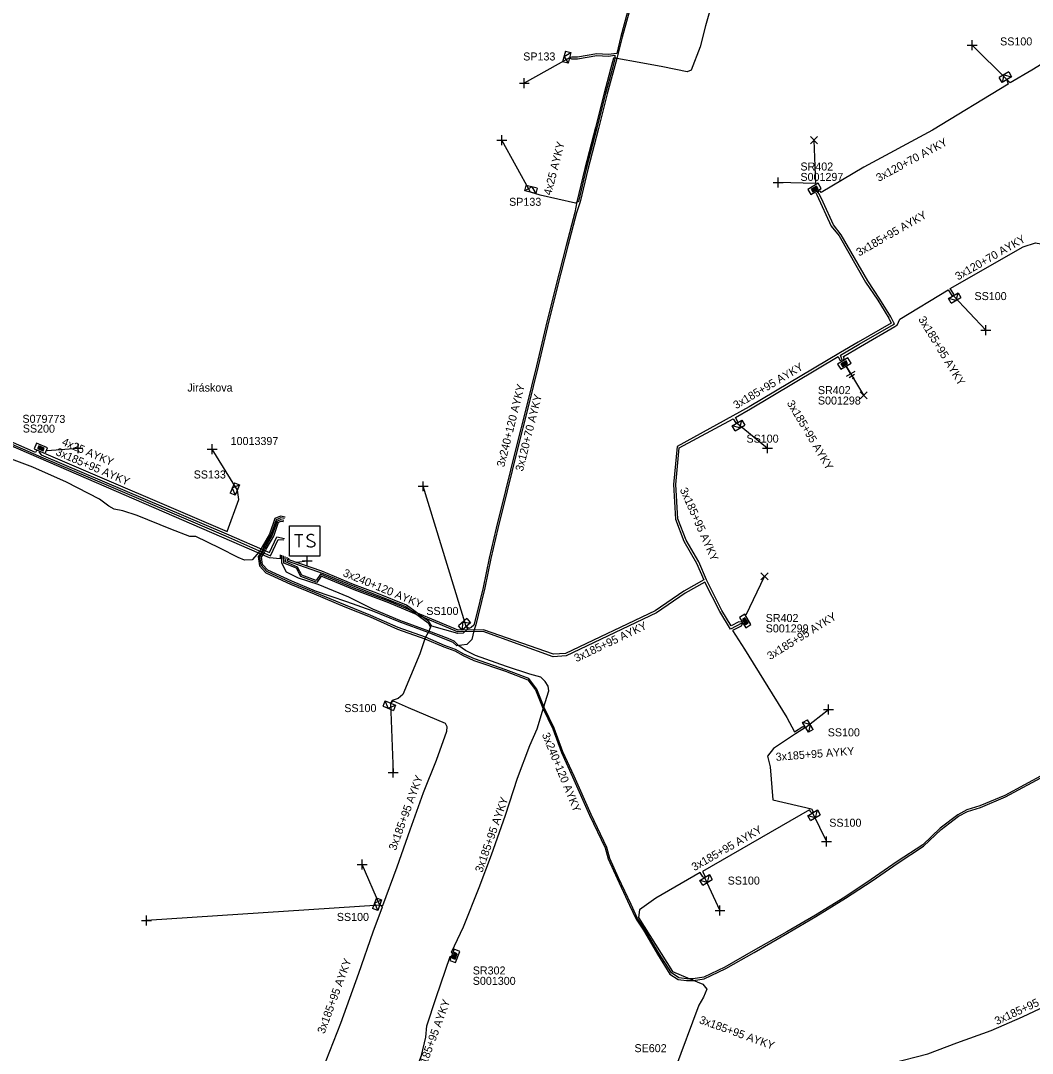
# Model space of a CAD drawing. Extents: x -763093 to -760976, y -1155572 to -1152009.
# Drawn here: x -762038.3 to -761911.9, y -1154879.5 to -1154750.4 of the extents above; entities that cross this region are included whole.
import ezdxf

# ---------------------------------------------------------------- set-up
doc = ezdxf.new("R2010")
doc.units = 0
for name, color, linetype in [('Vrstva 1', 7, 'Continuous'), ('Vrstva 14', 7, 'Continuous'), ('Vrstva 15', 7, 'Continuous'), ('Vrstva 25', 7, 'Continuous'), ('Vrstva 26', 7, 'Continuous'), ('Vrstva 27', 7, 'Continuous'), ('Vrstva 28', 7, 'Continuous'), ('Vrstva 29', 7, 'Continuous'), ('Vrstva 30', 7, 'Continuous'), ('Vrstva 31', 7, 'Continuous'), ('Vrstva 33', 7, 'Continuous'), ('Vrstva 34', 7, 'Continuous'), ('Vrstva 5', 7, 'Continuous'), ('Vrstva 59', 7, 'Continuous'), ('Vrstva 6', 7, 'Continuous'), ('Vrstva 8', 7, 'Continuous'), ('Vrstva 9', 7, 'Continuous')]:
    doc.layers.add(name, color=color, linetype=linetype)

# ---------------------------------------------------------------- blocks, each defined once
blk = doc.blocks.new('NN800')
at = {"layer": 'Vrstva 1'}
for points in [[(-0.44, 0.44), (0.44, -0.44)], [(-0.44, -0.44), (0.44, 0.44)]]:
    blk.add_lwpolyline(points, dxfattribs=at)
blk = doc.blocks.new('NN620')
at = {"layer": 'Vrstva 8'}
for points in [[(0.75, 0), (-0.75, 0)], [(-0.75, 0), (-0.75, -0.75)], [(0.75, -0.75), (0.75, 0)], [(-0.75, -0.75), (0.75, -0.75)], [(0.37, -0.18), (-0.38, -0.18)], [(-0.38, -0.18), (-0.38, -0.56)], [(-0.38, -0.56), (0.37, -0.56)], [(0.32, -0.23), (-0.33, -0.23)], [(-0.33, -0.23), (-0.33, -0.51)], [(-0.33, -0.51), (0.32, -0.51)], [(0.27, -0.27), (-0.28, -0.27)], [(-0.28, -0.27), (-0.28, -0.46)], [(-0.28, -0.46), (0.27, -0.46)], [(0.23, -0.32), (-0.23, -0.32)], [(-0.23, -0.32), (-0.23, -0.42)], [(-0.23, -0.42), (0.23, -0.42)], [(-0.19, -0.37), (0.19, -0.37)], [(0.23, -0.42), (0.23, -0.32)], [(0.27, -0.46), (0.27, -0.27)], [(0.32, -0.51), (0.32, -0.23)], [(0.37, -0.56), (0.37, -0.18)]]:
    blk.add_lwpolyline(points, dxfattribs=at)
blk = doc.blocks.new('NN630')
at = {"layer": 'Vrstva 9'}
for points in [[(0, -0.7), (-0.7, 0)], [(-0.7, -0.7), (-0.7, 0), (0.7, 0), (0.7, -0.7)], [(-0.7, -0.7), (0.7, -0.7)], [(0, -0.7), (0.7, 0)]]:
    blk.add_lwpolyline(points, dxfattribs=at)
blk = doc.blocks.new('NN810')
at = {"layer": 'Vrstva 14'}
for points in [[(0, -0.64), (0, -1.89)], [(0.63, -1.89), (-0.62, -1.89)], [(0.39, -2.2), (-0.4, -2.2)], [(0, -2.52), (-0.12, -2.52)], [(0.14, -2.52), (0, -2.52)]]:
    blk.add_lwpolyline(points, dxfattribs=at)
blk = doc.blocks.new('NN640')
at = {"layer": 'Vrstva 6'}
for points in [[(-1.89, 1.89), (1.89, 1.89)], [(-1.89, -1.89), (-1.89, 1.89)], [(1.89, 1.89), (1.89, -1.89)], [(-1.26, 0.79), (-0.22, 0.79)], [(-0.73, 0.79), (-0.73, -0.79)], [(1.2, 0.66), (0.94, 0.79), (0.66, 0.79), (0.41, 0.66), (0.28, 0.47), (0.28, 0.41), (0.41, 0.22), (1.13, -0.16), (1.26, -0.32), (1.26, -0.47), (1.13, -0.66), (0.91, -0.79), (0.63, -0.79), (0.5, -0.73), (0.28, -0.6)], [(1.89, -1.89), (-1.89, -1.89)]]:
    blk.add_lwpolyline(points, dxfattribs=at)

msp = doc.modelspace()

# ---------------------------------------------------------------- linework, layer by layer
at = {"layer": 'Vrstva 5'}
for points in [[(-761951, -1154744.92), (-761952.76, -1154751.08), (-761953.43, -1154753.72), (-761954.52, -1154756.65), (-761955.04, -1154756.86), (-761958.1, -1154756.22), (-761961.03, -1154755.67), (-761963.82, -1154755.16), (-761963.92, -1154755.14), (-761964.25, -1154755.13), (-761964.6, -1154756.5), (-761965.42, -1154759.49), (-761966.51, -1154763.8), (-761967.84, -1154768.93), (-761968.81, -1154773.09), (-761969.08, -1154774.42), (-761970.16, -1154778.52), (-761971.44, -1154783.56), (-761972.7, -1154788.62), (-761973.86, -1154793.57), (-761975.12, -1154798.66), (-761976.49, -1154804.09), (-761977.73, -1154809.16), (-761978.91, -1154813.86), (-761979.76, -1154817.62), (-761980.53, -1154821.27), (-761981.36, -1154824.7), (-761981.67, -1154825.98), (-761982.02, -1154826.25), (-761982.31, -1154826.4), (-761982.63, -1154826.13), (-761982.49, -1154826.49), (-761983.04, -1154826.98), (-761983.69, -1154827), (-761986.95, -1154826.09), (-761987.31, -1154825.5), (-761990.09, -1154823.48), (-761993.79, -1154821.99), (-761996.71, -1154820.88), (-762000.66, -1154819.24), (-762004.8, -1154817.8), (-762004.81, -1154817.6)], [(-761961.87, -1154747.79), (-761963.14, -1154752.5), (-761963.82, -1154755.16), (-761965.04, -1154759.59), (-761966.13, -1154763.9), (-761967.46, -1154769.03), (-761968.41, -1154773.1), (-761968.88, -1154774.47), (-761969.96, -1154778.58), (-761971.24, -1154783.6), (-761972.5, -1154788.66), (-761973.66, -1154793.61), (-761974.92, -1154798.7), (-761976.29, -1154804.13), (-761977.53, -1154809.2), (-761978.71, -1154813.9), (-761979.56, -1154817.66), (-761980.33, -1154821.31), (-761981.16, -1154824.74), (-761981.45, -1154825.94), (-761981.68, -1154826.7), (-761981.95, -1154827.77), (-761982.57, -1154828.4), (-761983.82, -1154828.58), (-761984.25, -1154828.13), (-761984.97, -1154827.84), (-761987.39, -1154826.9), (-761991.02, -1154825.57), (-761994.38, -1154824.17), (-761997.55, -1154823.07), (-762001.48, -1154821.71), (-762004.43, -1154820.49), (-762007.42, -1154819.12), (-762008.07, -1154818.4), (-762008.21, -1154817.47), (-762007.9, -1154817.05), (-762007.62, -1154816.48), (-762006.68, -1154814.87), (-762006.07, -1154813.11), (-762005.76, -1154812.97), (-762005.48, -1154813.03)], [(-761962.07, -1154747.75), (-761963.34, -1154752.44), (-761963.82, -1154754.53), (-761964.91, -1154754.68), (-761966.33, -1154754.6), (-761968.75, -1154755.01), (-761969.45, -1154755.01), (-761969.74, -1154755.1), (-761969.47, -1154755.21), (-761968.73, -1154755.21), (-761966.31, -1154754.8), (-761964.91, -1154754.88), (-761964.08, -1154754.77), (-761964.06, -1154755.18), (-761964.41, -1154756.55), (-761965.23, -1154759.54), (-761966.32, -1154763.85), (-761967.65, -1154768.98), (-761968.6, -1154773.05), (-761968.98, -1154773.27), (-761973.39, -1154772.25), (-761974.62, -1154771.89)], [(-761908.65, -1154754.61), (-761911.99, -1154756.63), (-761914.71, -1154758.2), (-761915.11, -1154757.81)], [(-762181.23, -1154758.53), (-762171.67, -1154757.36), (-762165.37, -1154757.31), (-762159.93, -1154757.58), (-762150.92, -1154758.82), (-762136.22, -1154763.17), (-762128.28, -1154765.54), (-762121.5, -1154768.45), (-762108.38, -1154774.11), (-762101.51, -1154777.12), (-762093.99, -1154780.16), (-762079.09, -1154786.61), (-762062.62, -1154793.49), (-762050.39, -1154798.57), (-762036.07, -1154804.84), (-762027.38, -1154808.52), (-762012.7, -1154814.81), (-762007.08, -1154817.32), (-762006.12, -1154815.27), (-762005.4, -1154815.32)], [(-761915.11, -1154757.81), (-761914.95, -1154758.38), (-761924.41, -1154764.13), (-761932.97, -1154768.74), (-761938.31, -1154771.92), (-761938.43, -1154771.76), (-761938.75, -1154771.83)], [(-761938.98, -1154771.97), (-761938.94, -1154772.04), (-761938.84, -1154772.2), (-761937.04, -1154776.12), (-761936.04, -1154777.35), (-761932.75, -1154783.1), (-761931.23, -1154785.39), (-761929.87, -1154787.62), (-761929.54, -1154788.23), (-761933.69, -1154790.62), (-761935.89, -1154791.9), (-761947.3, -1154798.68), (-761956.3, -1154803.65), (-761956.75, -1154808.4), (-761956.49, -1154812.74), (-761955.44, -1154815.49), (-761953.86, -1154818.22), (-761952.94, -1154820.31), (-761955.44, -1154821.73), (-761959.04, -1154824.17), (-761970.23, -1154829.5), (-761971.73, -1154829.62), (-761980.47, -1154826.57), (-761983.63, -1154826.61), (-761992.22, -1154823.02), (-761996.56, -1154821.38), (-762000.82, -1154819.61), (-762001.38, -1154820.4), (-762003.17, -1154819.72), (-762003.7, -1154818.71), (-762005.23, -1154818.07), (-762005.25, -1154817.41)], [(-761935.67, -1154792.86), (-761935.9, -1154792.26), (-761933.55, -1154790.88), (-761929.27, -1154788.41), (-761929.14, -1154788.33), (-761929.21, -1154788.21), (-761929.61, -1154787.47), (-761930.97, -1154785.23), (-761932.49, -1154782.94), (-761935.8, -1154777.19), (-761936.78, -1154775.96), (-761938.07, -1154773.14), (-761938.57, -1154772.07), (-761938.7, -1154771.89), (-761938.86, -1154771.9)], [(-761921.81, -1154784.8), (-761921.75, -1154784.6), (-761922.17, -1154783.92), (-761913.09, -1154778.7), (-761911.53, -1154778.2), (-761909.53, -1154778.59), (-761907.79, -1154780.05), (-761903.33, -1154784.19), (-761898.58, -1154793.13), (-761899.39, -1154793.63), (-761899.45, -1154793.83)], [(-761935.55, -1154792.79), (-761935.41, -1154792.66), (-761935.53, -1154792.4), (-761933.39, -1154791.14), (-761929.11, -1154788.67), (-761928.97, -1154788.57), (-761928.8, -1154788.48), (-761928.48, -1154787.75), (-761922.42, -1154784.07), (-761922, -1154784.77), (-761921.81, -1154784.8)], [(-761948.29, -1154825.6), (-761948.57, -1154825.55), (-761949.54, -1154826.07), (-761950.7, -1154824.14), (-761952.61, -1154820.31), (-761953.6, -1154818.08), (-761955.16, -1154815.35), (-761956.19, -1154812.68), (-761956.45, -1154808.4), (-761956.02, -1154803.83), (-761949.29, -1154800.2), (-761949.02, -1154800.67), (-761948.8, -1154800.73), (-761948.76, -1154800.5), (-761949.01, -1154800.04), (-761947.14, -1154798.94), (-761936.16, -1154792.41), (-761935.97, -1154792.88), (-761935.78, -1154792.92)], [(-762036.31, -1154804.17), (-762036.42, -1154804.4), (-762050.29, -1154798.32), (-762056.33, -1154795.78), (-762056.42, -1154795.39)], [(-762005.89, -1154817.17), (-762005.88, -1154817.68), (-762007.21, -1154817.56), (-762050.49, -1154798.83), (-762054.9, -1154809.94), (-762056.15, -1154809.6)], [(-762005.24, -1154812.47), (-762005.84, -1154812.35), (-762006.55, -1154812.67), (-762007.22, -1154814.61), (-762008.14, -1154816.2), (-762008.44, -1154816.79), (-762009.38, -1154817.81), (-762010.33, -1154817.84), (-762011.13, -1154817.52), (-762013.43, -1154816.35), (-762016.41, -1154814.91), (-762017.17, -1154814.89), (-762019.52, -1154813.97), (-762023.73, -1154812.27), (-762025.53, -1154811.68), (-762026.63, -1154811.49), (-762027.29, -1154811.1), (-762028.44, -1154810.22), (-762032.58, -1154808.12), (-762036.78, -1154806.22), (-762042.03, -1154804.26)], [(-762036.01, -1154804.32), (-762035.75, -1154804.69), (-762012.6, -1154814.56), (-762007.23, -1154816.91), (-762006.3, -1154814.93), (-762005.33, -1154815.14)], [(-762035.15, -1154804.59), (-762012.48, -1154814.28), (-762011.03, -1154810.29), (-762011.22, -1154809.1)], [(-762005.32, -1154812.65), (-762005.81, -1154812.56), (-762006.39, -1154812.82), (-762007.04, -1154814.7), (-762007.97, -1154816.29), (-762008.26, -1154816.88), (-762008.63, -1154817.41), (-762008.45, -1154818.58), (-762007.66, -1154819.44), (-762004.59, -1154820.85), (-762001.64, -1154822.07), (-761997.81, -1154823.67), (-761994.64, -1154824.94), (-761991.24, -1154826.46), (-761987.79, -1154827.67), (-761985.42, -1154828.7), (-761984.05, -1154829.19), (-761983.02, -1154829.76), (-761981.69, -1154830.38), (-761977.74, -1154831.74), (-761974.94, -1154832.82), (-761974, -1154834.07), (-761973.08, -1154836.33), (-761971.83, -1154838.92), (-761970.75, -1154841.87), (-761969.35, -1154844.92), (-761967.23, -1154849.71), (-761965.27, -1154853.81), (-761964.9, -1154855.18), (-761963.78, -1154857.62), (-761962.23, -1154860.98), (-761961.39, -1154862.72), (-761960.49, -1154864.1), (-761958.76, -1154867.07), (-761957.19, -1154869.57), (-761956.18, -1154870.25), (-761955.12, -1154870.37), (-761954.26, -1154870.38), (-761952.91, -1154870.16), (-761950.23, -1154868.87), (-761946.68, -1154866.86), (-761942.5, -1154864.46), (-761938.95, -1154862.37), (-761935.25, -1154860.1), (-761931.94, -1154857.92), (-761928.68, -1154855.66), (-761925.52, -1154853.58), (-761923.33, -1154851.52), (-761921.13, -1154849.85), (-761920.01, -1154849.25), (-761918.42, -1154848.75), (-761915.28, -1154847.44), (-761910.33, -1154844.78)], [(-761910.43, -1154844.6), (-761915.36, -1154847.26), (-761918.48, -1154848.57), (-761920.09, -1154849.07), (-761921.23, -1154849.69), (-761923.45, -1154851.36), (-761925.62, -1154853.44), (-761928.8, -1154855.5), (-761932.06, -1154857.76), (-761935.34, -1154859.96), (-761939.01, -1154862.21), (-761942.6, -1154864.28), (-761946.78, -1154866.68), (-761950.33, -1154868.69), (-761952.97, -1154869.96), (-761954.28, -1154870.18), (-761955.09, -1154870.15), (-761956.1, -1154870.05), (-761956.99, -1154869.41), (-761958.6, -1154866.97), (-761960.31, -1154864), (-761961.24, -1154862.61), (-761962.05, -1154860.88), (-761963.6, -1154857.54), (-761964.72, -1154855.12), (-761965.09, -1154853.75), (-761967.05, -1154849.63), (-761969.17, -1154844.84), (-761970.57, -1154841.79), (-761971.65, -1154838.84), (-761972.9, -1154836.25), (-761973.82, -1154833.97), (-761974.82, -1154832.66), (-761977.68, -1154831.56), (-761981.61, -1154830.2), (-761982.92, -1154829.58), (-761983.97, -1154829.01), (-761985.34, -1154828.52), (-761987.72, -1154827.49), (-761991.16, -1154826.28), (-761994.56, -1154824.76), (-761997.73, -1154823.49), (-762001.56, -1154821.89), (-762004.51, -1154820.67), (-762007.54, -1154819.28), (-762008.26, -1154818.49), (-762008.42, -1154817.44), (-762008.08, -1154816.96), (-762007.79, -1154816.39), (-762006.86, -1154814.78), (-762006.23, -1154812.96), (-762005.79, -1154812.76), (-762005.4, -1154812.84)], [(-761984.4, -1154867.02), (-761984.46, -1154866.85), (-761982.99, -1154863.65), (-761981.02, -1154858.76), (-761979.47, -1154854.69), (-761977.75, -1154849.7), (-761976.25, -1154845.11), (-761974.68, -1154841.01), (-761973.78, -1154838.91), (-761972.99, -1154836.29), (-761972.31, -1154834.18), (-761972.4, -1154833.61), (-761972.77, -1154833.01), (-761973.33, -1154832.48), (-761974.68, -1154832.08), (-761977.61, -1154831.15), (-761981.48, -1154829.78), (-761982.74, -1154829.13), (-761983.58, -1154828.54), (-761984.13, -1154827.97), (-761984.89, -1154827.66), (-761987.32, -1154826.72), (-761990.94, -1154825.39), (-761994.3, -1154823.99), (-761997.29, -1154822.46), (-762001.15, -1154820.9), (-762003.59, -1154820.12), (-762005.08, -1154819.36), (-762005.41, -1154818.72), (-762005.66, -1154818.2), (-762005.67, -1154817.25)], [(-761948.22, -1154825.72), (-761949.64, -1154826.47), (-761950.96, -1154824.28), (-761952.83, -1154820.59), (-761955.28, -1154821.99), (-761958.89, -1154824.43), (-761970.15, -1154829.8), (-761971.77, -1154829.92), (-761980.51, -1154826.77), (-761983.71, -1154826.8), (-761992.3, -1154823.2), (-761996.64, -1154821.56), (-762000.74, -1154819.85), (-762001.3, -1154820.64), (-762003.31, -1154819.88), (-762003.85, -1154818.85), (-762005.44, -1154818.21), (-762005.45, -1154817.33)], [(-762005.03, -1154817.46), (-762005.02, -1154817.93), (-762000.49, -1154819.53), (-761996.78, -1154821.08), (-761993.88, -1154822.18), (-761990.18, -1154823.66), (-761987.41, -1154825.69), (-761987.12, -1154826.22), (-761987.35, -1154826.81), (-761987.76, -1154827.58), (-761988.42, -1154829.54), (-761989.59, -1154832.35), (-761990.54, -1154834.64), (-761991.13, -1154835.12), (-761991.88, -1154835.37), (-761992.11, -1154835.71)], [(-761948.16, -1154825.83), (-761948.3, -1154826.1), (-761949.36, -1154826.65), (-761947.89, -1154828.97), (-761942.6, -1154837.53), (-761941.63, -1154839.32), (-761940.58, -1154838.63), (-761940.26, -1154838.76), (-761941.49, -1154839.57), (-761944.27, -1154841.37), (-761945.01, -1154842.35), (-761944.66, -1154843.67), (-761944.34, -1154847.8), (-761939.51, -1154848.91), (-761939.33, -1154849.22), (-761939.38, -1154849.43), (-761939.6, -1154849.34), (-761939.77, -1154849.07), (-761953.14, -1154856.74), (-761952.83, -1154857.28), (-761952.86, -1154857.51), (-761953.09, -1154857.42), (-761953.4, -1154856.9), (-761958.94, -1154860.07), (-761960.99, -1154861.55), (-761961.1, -1154862.5), (-761956.88, -1154869.27), (-761955, -1154870.05), (-761953.08, -1154870.83), (-761952.6, -1154871.45), (-761952.99, -1154872.45), (-761953.59, -1154873.47), (-761956.61, -1154881.61)], [(-762000.61, -1154881.53), (-761998.29, -1154875.7), (-761996.07, -1154869.45), (-761994.25, -1154864.29), (-761993.11, -1154861.18), (-761993.45, -1154860.96), (-761993.05, -1154861), (-761991.27, -1154856.18), (-761989.63, -1154851.56), (-761987.96, -1154846.87), (-761986.34, -1154842.83), (-761985.08, -1154839.22), (-761985.02, -1154838.68), (-761985.24, -1154838.27), (-761989.86, -1154836.3), (-761991.71, -1154835.49), (-761992.11, -1154835.71)], [(-761974.73, -1154896.45), (-761976.02, -1154895.81), (-761976.32, -1154895.51), (-761977.72, -1154894), (-761979.19, -1154893.19), (-761982.07, -1154892.21), (-761985.55, -1154890.91), (-761988.08, -1154889.86), (-761989.57, -1154888.98), (-761990.38, -1154888.36), (-761990.79, -1154887.53), (-761990.9, -1154886.94), (-761989.13, -1154882.18), (-761988.22, -1154879.75), (-761987.67, -1154877.45), (-761987.55, -1154876.02), (-761986.41, -1154872.5), (-761984.64, -1154867.37), (-761984.51, -1154867.33)], [(-761956.76, -1154882.91), (-761956.39, -1154882.34), (-761954.93, -1154882.94), (-761954.29, -1154883.46), (-761952.44, -1154884.41), (-761950.63, -1154885.21), (-761949.5, -1154885.6), (-761948.02, -1154886.05), (-761944.39, -1154886.5), (-761942.75, -1154886.42), (-761940.62, -1154885.57), (-761937.48, -1154884.38), (-761933.96, -1154883.07), (-761930.85, -1154881.32), (-761929.51, -1154880.69), (-761924.98, -1154879.55), (-761921.37, -1154878.15), (-761917.08, -1154876.64), (-761913.14, -1154874.9), (-761909.53, -1154873.22)]]:
    msp.add_lwpolyline(points, dxfattribs=at)
at = {"layer": 'Vrstva 59'}
for points in [[(-761915.11, -1154757.81), (-761919.44, -1154753.5)], [(-761969.74, -1154755.1), (-761975.38, -1154758.25)], [(-761974.62, -1154771.89), (-761978.19, -1154765.38)], [(-761938.97, -1154770.79), (-761939.19, -1154765.38)], [(-761938.97, -1154770.79), (-761943.66, -1154770.68)], [(-761921.81, -1154784.8), (-761917.75, -1154789.13)], [(-761935.14, -1154793.72), (-761933, -1154797.25)], [(-761948.8, -1154800.73), (-761945, -1154803.88)], [(-762035, -1154804.16), (-762031.13, -1154803.88)], [(-762011.22, -1154809.1), (-762014.38, -1154804)], [(-761982.63, -1154826.13), (-761988, -1154808.63)], [(-762003.79, -1154818.1), (-762002.5, -1154817.95)], [(-761947.66, -1154824.69), (-761945.38, -1154819.88)], [(-761992.11, -1154835.71), (-761991.75, -1154844.38)], [(-761940.26, -1154838.76), (-761937.38, -1154836.5)], [(-761939.38, -1154849.43), (-761937.63, -1154853)], [(-761993.45, -1154860.96), (-761995.63, -1154855.88)], [(-761952.86, -1154857.51), (-761950.94, -1154861.63)], [(-761993.45, -1154860.96), (-762022.59, -1154862.88)]]:
    msp.add_lwpolyline(points, dxfattribs=at)

# ---------------------------------------------------------------- block references
at = {"layer": 'Vrstva 15', "rotation": 30.570686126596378}
msp.add_blockref('NN810', (-761935.6, -1154792.97), dxfattribs=at)
at = {"layer": 'Vrstva 25'}
msp.add_blockref('NN640', (-762002.82, -1154815.45), dxfattribs=at)
at = {"layer": 'Vrstva 28'}
for p, rotation in [((-761938.93, -1154771.79), -148.88466670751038), ((-761935.6, -1154792.97), 30.570686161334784), ((-762035.91, -1154804.22), 156.89616102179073), ((-761948.11, -1154825.65), 120.78610562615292), ((-761984.41, -1154867.17), 69.21410832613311)]:
    msp.add_blockref('NN620', p, dxfattribs=dict(at, rotation=rotation))
at = {"layer": 'Vrstva 31'}
for p, rotation in [((-761969.74, -1154755.1), -104.44502495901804), ((-761915.11, -1154757.81), -149.1991360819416), ((-761974.62, -1154771.89), 166.68391676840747), ((-761921.81, -1154784.8), 30.600311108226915), ((-761948.8, -1154800.73), 30.589038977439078), ((-762011.22, -1154809.1), -112.53678891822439), ((-761982.63, -1154826.13), -139.00390832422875), ((-761992.11, -1154835.71), -22.965094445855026), ((-761940.26, -1154838.76), 120.75540827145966), ((-761939.38, -1154849.43), 30.83461380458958), ((-761952.86, -1154857.51), 30.896399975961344), ((-761993.45, -1154860.96), -110.19263606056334)]:
    msp.add_blockref('NN630', p, dxfattribs=dict(at, rotation=rotation))
at = {"layer": 'Vrstva 34'}
for p, rotation in [((-761919.44, -1154753.5), 44.99999995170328), ((-761975.38, -1154758.25), 45), ((-761978.19, -1154765.38), 44.99999995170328), ((-761943.66, -1154770.68), 45), ((-761917.75, -1154789.13), 45), ((-762031.13, -1154803.88), 45), ((-762014.38, -1154804), 45), ((-761945, -1154803.88), 45), ((-761988, -1154808.63), 45), ((-762002.5, -1154817.95), 45), ((-761937.38, -1154836.5), 45), ((-761991.75, -1154844.38), 45), ((-761937.63, -1154853), 45), ((-761995.63, -1154855.88), 45), ((-761950.94, -1154861.63), 44.99999995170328), ((-762022.59, -1154862.88), 45)]:
    msp.add_blockref('NN800', p, dxfattribs=dict(at, rotation=rotation))
for p in [(-761939.19, -1154765.38), (-761933, -1154797.25), (-761945.38, -1154819.88)]:
    msp.add_blockref('NN800', p, dxfattribs=at)

# ---------------------------------------------------------------- texts
at = {"layer": 'Vrstva 26'}
msp.add_text('10013397', height=1, dxfattribs=at).set_placement((-762012.06, -1154803.47))
at = {"layer": 'Vrstva 27'}
msp.add_text('Jiráskova', height=1, dxfattribs=at).set_placement((-762017.47, -1154796.79))
at = {"layer": 'Vrstva 29'}
for s, p in [('S001297', (-761940.89, -1154770.47)), ('S001298', (-761938.71, -1154798.41)), ('S001299', (-761945.23, -1154826.88)), ('S001300', (-761981.82, -1154870.92))]:
    msp.add_text(s, height=1, dxfattribs=at).set_placement(p)
msp.add_text('S079773', height=1, rotation=359.753, dxfattribs=at).set_placement((-762038.07, -1154800.69))
at = {"layer": 'Vrstva 30'}
for s, p in [('SR402', (-761940.89, -1154769.17)), ('SR402', (-761938.71, -1154797.11)), ('SR402', (-761945.23, -1154825.58)), ('SR302', (-761981.82, -1154869.62)), ('SE602', (-761961.62, -1154879.33))]:
    msp.add_text(s, height=1, dxfattribs=at).set_placement(p)
msp.add_text('SS200', height=1, rotation=359.495, dxfattribs=at).set_placement((-762038.03, -1154801.9))
at = {"layer": 'Vrstva 33'}
for s, p in [('SS100', (-761915.95, -1154753.54)), ('SP133', (-761975.52, -1154755.42)), ('SP133', (-761977.28, -1154773.58)), ('SS100', (-761919.15, -1154785.36)), ('SS100', (-761947.63, -1154803.17)), ('SS133', (-762016.68, -1154807.65)), ('SS100', (-761987.62, -1154824.7)), ('SS100', (-761997.87, -1154836.84)), ('SS100', (-761937.48, -1154839.87)), ('SS100', (-761937.29, -1154851.16)), ('SS100', (-761949.98, -1154858.39)), ('SS100', (-761998.8, -1154862.93))]:
    msp.add_text(s, height=1, dxfattribs=at).set_placement(p)
at = {"layer": 'Vrstva 6'}
for s, rotation, p in [('3x120+70 AYKY', 28.305, (-761931.11, -1154770.6)), ('4x25 AYKY', 75.657, (-761972.03, -1154772.33)), ('3x185+95 AYKY', 29.856, (-761933.56, -1154779.92)), ('3x120+70 AYKY', 29.919, (-761921.21, -1154782.92)), ('3x185+95 AYKY', 301.317, (-761926.21, -1154787.74)), ('3x185+95 AYKY', 30.719, (-761948.91, -1154799.01)), ('3x240+120 AYKY', 75.95, (-761977.89, -1154806.29)), ('3x120+70 AYKY', 75.972, (-761975.56, -1154806.82)), ('3x185+95 AYKY', 300.73, (-761942.63, -1154798.23)), ('3x185+95 AYKY', 336.896, (-762034, -1154804.69)), ('4x25 AYKY', 336.862, (-762033.23, -1154803.43)), ('3x185+95 AYKY', 293.817, (-761955.98, -1154809.05)), ('3x240+120 AYKY', 337.422, (-761998.12, -1154819.81)), ('3x185+95 AYKY', 31.718, (-761944.67, -1154830.35)), ('3x185+95 AYKY', 25.468, (-761968.87, -1154830.62)), ('3x240+120 AYKY', 292.324, (-761973.21, -1154839.64)), ('3x185+95 AYKY', 4.431, (-761943.94, -1154842.94)), ('3x185+95 AYKY', 69.812, (-761991.43, -1154854.2)), ('3x185+95 AYKY', 70.629, (-761980.64, -1154856.96)), ('3x185+95 AYKY', 29.861, (-761954.13, -1154856.72)), ('3x185+95 AYKY', 69.807, (-762000.35, -1154877.1)), ('3x185+95 AYKY', 24.77, (-761916.35, -1154875.95)), ('3x185+95 AYKY', 69.754, (-761988.03, -1154882.2)), ('3x185+95 AYKY', 340.136, (-761953.62, -1154875.68))]:
    msp.add_text(s, height=1, rotation=rotation, dxfattribs=at).set_placement(p)

doc.saveas('drawing.dxf')
